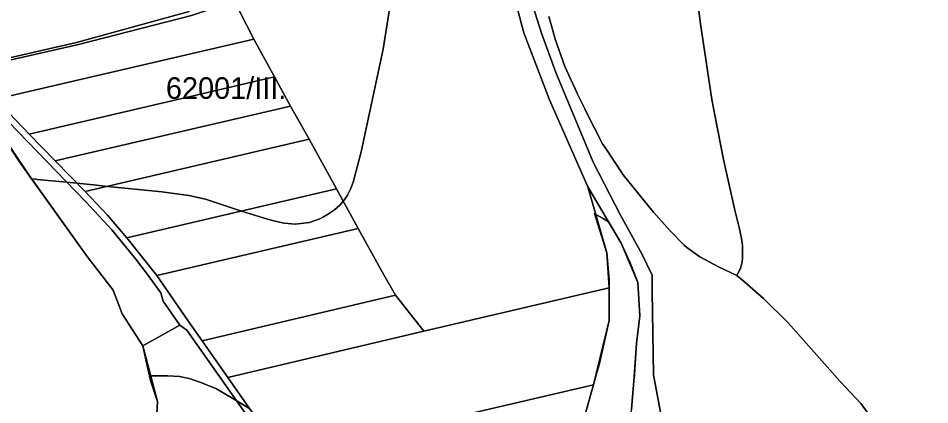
# Model space of a CAD drawing. Extents: x -521939 to -516426, y -1197857 to -1189551.
# Drawn here: x -519365 to -518732, y -1193670 to -1193402 of the extents above; entities that cross this region are included whole.
import ezdxf

# ---------------------------------------------------------------- set-up
doc = ezdxf.new("R2010")
doc.units = 0
for name, color, linetype in [('95600013', 7, 'Continuous'), ('95610013', 7, 'Continuous'), ('95620013', 7, 'Continuous'), ('95640013', 7, 'Continuous'), ('95660013', 7, 'Continuous')]:
    doc.layers.add(name, color=color, linetype=linetype)

msp = doc.modelspace()

# ---------------------------------------------------------------- linework, layer by layer
at = {"layer": '95600013'}
msp.add_lwpolyline([(-518704.53, -1193662.76), (-518731.88, -1193727.36), (-518745.46, -1193758.59), (-518905.61, -1193720.26), (-518906.72, -1193704.58), (-518916.83, -1193685.28), (-518923.59, -1193649.53), (-518924.44, -1193591.77), (-518924.55, -1193580.35), (-518931.74, -1193565.63), (-518946.48, -1193538.74), (-518965.5, -1193501.95), (-518991.48, -1193439.69), (-519001.34, -1193412.48), (-519007.46, -1193393.47)], dxfattribs=at)
at = {"layer": '95610013'}
for points in [[(-519216.77, -1193386.17), (-519201.14, -1193416.51), (-519380.85, -1193458.26), (-519400.65, -1193437.87), (-519323.14, -1193420.3), (-519244.63, -1193400.06), (-519224.13, -1193393.57)], [(-519186.96, -1193442.78), (-519357.29, -1193482.57), (-519380.85, -1193458.26), (-519201.14, -1193416.51)], [(-519405.79, -1193439.04), (-519317.99, -1193529.4), (-519300.03, -1193548.89), (-519283.14, -1193569.31), (-519275.11, -1193579.85), (-519265.95, -1193592.56), (-519264.31, -1193598.43), (-519252.73, -1193614.95), (-519278.45, -1193629.39), (-519292.71, -1193607.08), (-519298.97, -1193590.8), (-519316.99, -1193567.29), (-519355.68, -1193513.49), (-519383.3, -1193472.91), (-519402.88, -1193446.79)], [(-519186.96, -1193442.78), (-519175.78, -1193463.01), (-519339.22, -1193501.11), (-519357.29, -1193482.57)], [(-519339.22, -1193501.11), (-519175.78, -1193463.01), (-519162.86, -1193486.08), (-519318.54, -1193522.39)], [(-519143.89, -1193520.55), (-519289.45, -1193554.35), (-519302.97, -1193538.77), (-519318.54, -1193522.39), (-519162.86, -1193486.08)], [(-519128.68, -1193547.96), (-519268.66, -1193580.6), (-519289.45, -1193554.35), (-519143.89, -1193520.55)], [(-519237.09, -1193625.95), (-519247.12, -1193611.76), (-519268.66, -1193580.6), (-519128.68, -1193547.96), (-519110.84, -1193580.01), (-519102.82, -1193594.23)], [(-519083.02, -1193619.12), (-518954.36, -1193589.13), (-518954.36, -1193611.78), (-518965.26, -1193656.42), (-519003.05, -1193665.21), (-519180.65, -1193706.52), (-519219.36, -1193651.4)], [(-519219.36, -1193651.4), (-519237.09, -1193625.95), (-519102.82, -1193594.23), (-519083.02, -1193619.12)], [(-519252.73, -1193614.95), (-519247.85, -1193618.43), (-519207.59, -1193675.65), (-519266.62, -1193736.71), (-519270.68, -1193715.28), (-519268.16, -1193667.94), (-519278.45, -1193629.39)], [(-518965.26, -1193656.42), (-518977.05, -1193698.16), (-519157.44, -1193739.69), (-519180.65, -1193706.52), (-519003.05, -1193665.21)]]:
    msp.add_lwpolyline(points, close=True, dxfattribs=at)
at = {"layer": '95620013'}
for points in [[(-519049.8, -1193274.26), (-519040.03, -1193304.65), (-519061.29, -1193334.23), (-519127.73, -1193353.98), (-519195.16, -1193370.61), (-519207.67, -1193377.01), (-519216.77, -1193386.17), (-519224.13, -1193393.57), (-519244.63, -1193400.06), (-519323.14, -1193420.3), (-519400.65, -1193437.87), (-519436.58, -1193400.77), (-519414.21, -1193393.4), (-519363, -1193379.33), (-519272.27, -1193354.6), (-519242.56, -1193344.82), (-519244.89, -1193329.7), (-519245.64, -1193323.44), (-519072.06, -1193279.85)], [(-519065.01, -1193870.53), (-519062.93, -1193818.34), (-519025.65, -1193756.19), (-519011.53, -1193738.42), (-518977.05, -1193698.16), (-518965.26, -1193656.42), (-518954.36, -1193611.78), (-518954.36, -1193589.13), (-518956.05, -1193564.77), (-518969.16, -1193519.14), (-518945.93, -1193558.15), (-518934.47, -1193585.52), (-518933.01, -1193608.51), (-518935.29, -1193627.86), (-518936.87, -1193650.95), (-518938.89, -1193673.47), (-518948.63, -1193706.4), (-518978.36, -1193751.04), (-519025.45, -1193817.42), (-519026.74, -1193837.39), (-519039.32, -1193871.96), (-519051.46, -1193885.31)]]:
    msp.add_lwpolyline(points, close=True, dxfattribs=at)
msp.add_lwpolyline([(-519383.3, -1193472.91), (-519355.68, -1193513.49), (-519316.99, -1193567.29), (-519298.97, -1193590.8), (-519292.71, -1193607.08), (-519278.45, -1193629.39), (-519268.16, -1193667.94), (-519270.68, -1193715.28)], dxfattribs=at)
at = {"layer": '95640013'}
msp.add_lwpolyline([(-519110.84, -1193580.01), (-519128.68, -1193547.96), (-519143.89, -1193520.55), (-519162.86, -1193486.08), (-519175.78, -1193463.01), (-519186.96, -1193442.78), (-519201.14, -1193416.51), (-519216.77, -1193386.17), (-519207.67, -1193377.01), (-519195.16, -1193370.61), (-519127.73, -1193353.98), (-519061.29, -1193334.23), (-519040.03, -1193304.65), (-519037.03, -1193315.32), (-519029.64, -1193352.06), (-519013.6, -1193412.23), (-518995.72, -1193458.59), (-518983.73, -1193485.98), (-518969.16, -1193519.14), (-518956.05, -1193564.77), (-518954.36, -1193589.13), (-519083.02, -1193619.12), (-519102.82, -1193594.23)], close=True, dxfattribs=at)
for points in [[(-518938.89, -1193673.47), (-518936.87, -1193650.95), (-518935.29, -1193627.86), (-518933.01, -1193608.51), (-518934.47, -1193585.52), (-518945.93, -1193558.15), (-518969.16, -1193519.14), (-518983.73, -1193485.98), (-518995.72, -1193458.59), (-519013.6, -1193412.23), (-519029.64, -1193352.06)], [(-519007.46, -1193393.47), (-519001.34, -1193412.48), (-518991.48, -1193439.69), (-518965.5, -1193501.95), (-518946.48, -1193538.74), (-518931.74, -1193565.63), (-518924.55, -1193580.35), (-518924.44, -1193591.77), (-518923.59, -1193649.53), (-518916.83, -1193685.28)], [(-519207.59, -1193675.65), (-519247.85, -1193618.43), (-519252.73, -1193614.95), (-519264.31, -1193598.43), (-519265.95, -1193592.56), (-519275.11, -1193579.85), (-519283.14, -1193569.31), (-519300.03, -1193548.89), (-519317.99, -1193529.4), (-519405.79, -1193439.04)], [(-519380.85, -1193458.26), (-519357.29, -1193482.57), (-519339.22, -1193501.11), (-519318.54, -1193522.39), (-519302.97, -1193538.77), (-519289.45, -1193554.35), (-519268.66, -1193580.6), (-519247.12, -1193611.76), (-519237.09, -1193625.95), (-519219.36, -1193651.4), (-519180.65, -1193706.52)]]:
    msp.add_lwpolyline(points, dxfattribs=at)
at = {"layer": '95660013'}
for points in [[(-518896.07, -1193366.91), (-518890.82, -1193405.87), (-518882.89, -1193458.47), (-518880.6, -1193470.44), (-518874.96, -1193500.03), (-518866.96, -1193535.27), (-518864.06, -1193547.32), (-518862.44, -1193554.97), (-518861.74, -1193559.73), (-518861.63, -1193563.78), (-518861.63, -1193565.12), (-518861.63, -1193567.96), (-518861.98, -1193571.55), (-518862.08, -1193571.95), (-518862.56, -1193573.81), (-518862.9, -1193574.88), (-518863.16, -1193575.69), (-518863.47, -1193576.44), (-518863.74, -1193577.08), (-518864.61, -1193578.82), (-518865.68, -1193580.59), (-518878.32, -1193574.56), (-518891.3, -1193567.72), (-518900.27, -1193561.04), (-518902.2, -1193559.61), (-518912.28, -1193549.41), (-518923.64, -1193536.54), (-518926.76, -1193532.69), (-518944.5, -1193510.81), (-518957.21, -1193491.86), (-518958.65, -1193489.72), (-518964.26, -1193478.86), (-518967.45, -1193472.68), (-518971.2, -1193465.04), (-518976.5, -1193454.25), (-518976.56, -1193454.11), (-518985.19, -1193435.59), (-518991.8, -1193416.69), (-518993.45, -1193410.66), (-518996.16, -1193400.77)], [(-518764.03, -1193690.5), (-518779.5, -1193669.41), (-518793.88, -1193654.11), (-518830.04, -1193613.31), (-518847.2, -1193596.61), (-518860.06, -1193585.26), (-518865.68, -1193580.59), (-518864.61, -1193578.82), (-518863.74, -1193577.08), (-518863.47, -1193576.44), (-518863.16, -1193575.69), (-518862.9, -1193574.88), (-518862.56, -1193573.81), (-518862.08, -1193571.95), (-518861.98, -1193571.55), (-518861.63, -1193567.96), (-518861.63, -1193565.12), (-518861.63, -1193563.78), (-518861.74, -1193559.73), (-518862.44, -1193554.97), (-518864.06, -1193547.32), (-518866.96, -1193535.27), (-518874.96, -1193500.03), (-518880.6, -1193470.44), (-518882.89, -1193458.47), (-518890.82, -1193405.87), (-518896.07, -1193366.91)], [(-519104.42, -1193379.31), (-519111.37, -1193423.59), (-519126.67, -1193494.76), (-519129.26, -1193504.57), (-519132.24, -1193515.85), (-519134.09, -1193520.72), (-519134.3, -1193521.14), (-519136.18, -1193524.89), (-519138.5, -1193528.37), (-519139.14, -1193529.11), (-519141.51, -1193531.85), (-519145.22, -1193535.1), (-519150.09, -1193538.34), (-519152.93, -1193539.95), (-519155.42, -1193541.35), (-519162.61, -1193543.9), (-519172.57, -1193545.06), (-519179.99, -1193544.37), (-519181.23, -1193544.1), (-519187.41, -1193542.75), (-519191.71, -1193541.43), (-519197.8, -1193539.55), (-519209.82, -1193535.86), (-519216.85, -1193533.7), (-519234.93, -1193527.68), (-519246.53, -1193525.13), (-519265.07, -1193522.58), (-519302.78, -1193518.72), (-519312.59, -1193517.71), (-519324.19, -1193516.58), (-519331.1, -1193515.9), (-519351.89, -1193513.87), (-519352.58, -1193513.8), (-519355.68, -1193513.49), (-519364.55, -1193501.1), (-519383.3, -1193472.91)], [(-519204.27, -1193672.88), (-519213.44, -1193667.34), (-519215.92, -1193665.84), (-519227.17, -1193659.12), (-519238.06, -1193654.83), (-519246.18, -1193652.05), (-519252.9, -1193650.66), (-519260.9, -1193650.19), (-519266.92, -1193650.24), (-519268.26, -1193650.25), (-519272.87, -1193650.29), (-519273.68, -1193650.3), (-519274.37, -1193647.27), (-519276.23, -1193639.09), (-519278.45, -1193629.39), (-519292.71, -1193607.08), (-519295.27, -1193600.42), (-519298.72, -1193591.45), (-519298.97, -1193590.8), (-519316.99, -1193567.29), (-519327.43, -1193552.77), (-519330.95, -1193548.07), (-519355.3, -1193514.02), (-519355.68, -1193513.49), (-519352.58, -1193513.8), (-519351.89, -1193513.87), (-519331.1, -1193515.9), (-519324.19, -1193516.58), (-519312.59, -1193517.71), (-519302.78, -1193518.72), (-519265.07, -1193522.58), (-519246.53, -1193525.13), (-519234.93, -1193527.68), (-519216.85, -1193533.7), (-519209.82, -1193535.86), (-519197.8, -1193539.55), (-519191.71, -1193541.43), (-519187.41, -1193542.75), (-519181.23, -1193544.1), (-519179.99, -1193544.37), (-519172.57, -1193545.06), (-519162.61, -1193543.9), (-519155.42, -1193541.35), (-519152.93, -1193539.95), (-519150.09, -1193538.34), (-519145.22, -1193535.1), (-519141.51, -1193531.85), (-519139.14, -1193529.11), (-519138.5, -1193528.37), (-519136.18, -1193524.89), (-519134.3, -1193521.14), (-519134.09, -1193520.72), (-519132.24, -1193515.85), (-519129.26, -1193504.57), (-519126.67, -1193494.76), (-519111.37, -1193423.59), (-519104.42, -1193379.31)], [(-519246.07, -1193397.49), (-519324.52, -1193418.94), (-519393.46, -1193434.71), (-519394.03, -1193434.06), (-519394.68, -1193433.31), (-519423.63, -1193400.22)], [(-519393.46, -1193434.71), (-519324.52, -1193418.94), (-519246.07, -1193397.49)], [(-518996.16, -1193400.77), (-518993.45, -1193410.66), (-518991.8, -1193416.69), (-518985.19, -1193435.59), (-518976.56, -1193454.11), (-518976.5, -1193454.25), (-518971.2, -1193465.04), (-518967.45, -1193472.68), (-518964.26, -1193478.86), (-518958.65, -1193489.72), (-518957.21, -1193491.86), (-518944.5, -1193510.81), (-518926.76, -1193532.69), (-518923.64, -1193536.54), (-518912.28, -1193549.41), (-518902.2, -1193559.61), (-518900.27, -1193561.04), (-518891.3, -1193567.72), (-518878.32, -1193574.56), (-518865.68, -1193580.59), (-518860.06, -1193585.26), (-518847.2, -1193596.61), (-518830.04, -1193613.31), (-518793.88, -1193654.11), (-518779.5, -1193669.41), (-518764.03, -1193690.5)], [(-519383.3, -1193472.91), (-519364.55, -1193501.1), (-519355.68, -1193513.49), (-519355.3, -1193514.02), (-519330.95, -1193548.07), (-519327.43, -1193552.77), (-519316.99, -1193567.29), (-519298.97, -1193590.8), (-519298.72, -1193591.45), (-519295.27, -1193600.42), (-519292.71, -1193607.08), (-519278.45, -1193629.39), (-519276.23, -1193639.09), (-519274.37, -1193647.27), (-519273.68, -1193650.3), (-519272.94, -1193653.52), (-519268.16, -1193667.94), (-519270.68, -1193715.28)], [(-518969.71, -1193672.16), (-518966.86, -1193662.08), (-518965.26, -1193656.42), (-518963.31, -1193649.5), (-518961.38, -1193642.67), (-518960.65, -1193639.46), (-518954.36, -1193611.78), (-518954.34, -1193589.13), (-518954.34, -1193583.7), (-518956.05, -1193564.77), (-518964.59, -1193537.64), (-518963.7, -1193538.16), (-518958.98, -1193540.89), (-518954.74, -1193543.35), (-518954.47, -1193543.51), (-518945.93, -1193558.15), (-518939.86, -1193571.25), (-518938.8, -1193574.05), (-518934.47, -1193585.52), (-518933.01, -1193608.51), (-518935.29, -1193627.86), (-518936.46, -1193645.17), (-518936.76, -1193649.57), (-518936.84, -1193650.58), (-518936.87, -1193650.95), (-518937.86, -1193661.96), (-518938.89, -1193673.47)], [(-518938.89, -1193673.47), (-518937.86, -1193661.96), (-518936.87, -1193650.95), (-518936.84, -1193650.58), (-518936.76, -1193649.57), (-518936.46, -1193645.17), (-518935.29, -1193627.86), (-518933.01, -1193608.51), (-518934.47, -1193585.52), (-518938.8, -1193574.05), (-518939.86, -1193571.25), (-518945.93, -1193558.15), (-518954.47, -1193543.51), (-518954.74, -1193543.35), (-518958.98, -1193540.89), (-518963.7, -1193538.16), (-518964.59, -1193537.64), (-518956.05, -1193564.77), (-518954.34, -1193583.7), (-518954.34, -1193589.13), (-518954.36, -1193611.78), (-518960.65, -1193639.46), (-518961.38, -1193642.67), (-518963.31, -1193649.5), (-518965.26, -1193656.42), (-518966.86, -1193662.08), (-518969.71, -1193672.16)], [(-519270.68, -1193715.28), (-519268.16, -1193667.94), (-519272.94, -1193653.52), (-519273.68, -1193650.3), (-519272.87, -1193650.29), (-519268.26, -1193650.25), (-519266.92, -1193650.24), (-519260.9, -1193650.19), (-519252.9, -1193650.66), (-519246.18, -1193652.05), (-519238.06, -1193654.83), (-519227.17, -1193659.12), (-519215.92, -1193665.84), (-519213.44, -1193667.34), (-519204.27, -1193672.88)]]:
    msp.add_lwpolyline(points, dxfattribs=at)

# ---------------------------------------------------------------- texts
msp.add_text('62001/III.', height=15, rotation=0, dxfattribs=at).set_placement((-519262.34, -1193458.02))

doc.saveas('drawing.dxf')
